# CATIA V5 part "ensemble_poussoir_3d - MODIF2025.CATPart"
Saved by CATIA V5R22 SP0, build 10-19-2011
Part number: Poussoir_flacon
Bounding box of the stored display mesh (mm): x 82 to 187, y 0 to 48, z 0 to 48
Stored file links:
  D:\PER\CAO_PER_MODIF_2025\CAO_PER_pick&place_2024P\Sous_Ensemble_Flacon\Verin\Poussoir_Flacon\ensemble_poussoir_3d - MODIF2025.CATPart
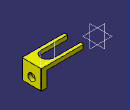
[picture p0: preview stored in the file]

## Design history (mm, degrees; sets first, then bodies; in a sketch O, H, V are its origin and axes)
Set1
  Plane1: type Offset, RefPlane face of Pocket3 from Sketch4.L1, Offset 16, reversed
Body1 (main body)
  Sketch1 on yz-plane, origin (0, 0, 0), H (0, 1, 0), V (0, 0, 1)
    line L1 (0, 0) -> (48, 0)
    line L2 (48, 0) -> (48, 48)
    line L3 (48, 48) -> (0, 48)
    line L4 (0, 48) -> (0, 0)
    point P1 (48, 0)
    point P2 (48, 48)
    point P3 (0, 48)
    distance P1 P2 = 48
    distance P2 P3 = 48
    horizontal: L1 H, L3 H
    vertical: L2 V, L4 V
  Pad1: profile Sketch1, direction (1, 0, 0), length 187
  Sketch2 on face of Pad1 from Sketch1.L4, origin (0, 0, 0), H (1, 0, 0), V (0, 0, 1)
    point P1 (15, 0)
    line L1 (15, 0) -> (173, 0)
    line L2 (173, 0) -> (173, 38)
    line L3 (173, 38) -> (15, 38)
    line L4 (15, 38) -> (15, 0)
    reference projected line E1 (0, 48) -> (187, 48) from edge [face of Pad1 from Sketch1.L4 | face of Pad1 from Sketch1.L3]
    reference projected line E2 (187, 48) -> (187, 0) from edge [face of Pad1 from Sketch1.L4 | end face of Pad1]
    reference projected line E3 (0, 48) -> (0, 0) from edge [start face of Pad1 | face of Pad1 from Sketch1.L4]
    distance L3 E1 = 10
    distance L2 E2 = 14
    distance L4 E3 = 15
    coincidence: P1 H
    horizontal: L1 H, L3 H
    vertical: L2 V, L4 V
  Pocket1: profile Sketch2, direction (0, 1, 0), through (limit type 3)
  Sketch3 on start face of Pad1, origin (0, 0, 0), H (0, -1, 0), V (0, 0, 1)
    line L1 (-41, 0) -> (-7, 0)
    line L2 (-7, 0) -> (-7, 31.5)
    line L3 (-41, 31.5) -> (-41, 0)
    point P2 (-7, 0)
    point P3 (-7, 49)
    point P4 (-41, 49)
    reference projected line E1 (0, 48) -> (0, 0) from edge [start face of Pad1 | face of Pad1 from Sketch1.L4]
    reference projected line E2 (-48, 0) -> (-48, 48) from edge [start face of Pad1 | face of Pad1 from Sketch1.L2]
    reference projected line E3 (0, 0) -> (-48, 0) from edge [start face of Pad1 | face of Pad1 from Sketch1.L1]
    point P5 (-7, 31.5)
    point P6 (-41, 31.5)
    arc A1 centre (-24, 25.5839) radius 18 from (-7, 31.5) to (-41, 31.5) ccw
    point P8 (-7, 31.5)
    point P9 (-41, 31.5)
    distance L2 E1 = 7
    distance L3 E2 = 7
    length L3 = 31.5
    radius A1 = 18
    distance P5 P2 = 31.5
    horizontal: L1 H
    vertical: L2 V, L3 V
    coincidence: E3 L1, L3 P6, L2 P5, P5 P8, P6 P9
  Pocket2: profile Sketch3, direction (1, 0, 0), up to face of Pocket1 from Sketch2.L4
  Sketch4 on face of Pad1 from Sketch1.L3, origin (0, 0, 48), H (1, 0, 0), V (0, 1, 0)
    point P1 (90, 24)
    line L1 (148, 8) -> (28, 8)
    line L2 (28, 40) -> (148, 40)
    point P3 (148, 8)
    point P4 (28, 8)
    arc A1 centre (148, 24) radius 16 from (148, 40) to (148, 8) cw
    arc A2 centre (28, 24) radius 16 from (28, 8) to (28, 40) cw
    point P7 (28, 24)
    reference projected line E1 (0, 48) -> (0, 0) from edge [start face of Pad1 | face of Pad1 from Sketch1.L3]
    distance L1 L2 = 32
    distance P3 P4 = 120
    radius A1 = 16
    radius A2 = 16
    distance P7 E1 = 28
    horizontal: L1 H, L2 H
    equidistance: L1 L2 P1
    fix: P1
  Pocket3: profile Sketch4, direction (0, 0, -1), through (limit type 3)
  Sketch5 on face of Pocket1 from Sketch2.L2, origin (173, 0, 0), H (0, 1, 0), V (0, 0, 1)
    circle A1 centre (24, 18) radius 4.25
    point P1 (24, 18)
    reference projected line E1 (48, 0) -> (48, 48) from edge [face of Pad1 from Sketch1.L2 | end face of Pad1]
    reference projected line E2 (0, 0) -> (48, 0) from edge [face of Pad1 from Sketch1.L1 | end face of Pad1]
    distance P1 E1 = 24
    radius A1 = 4.25
    distance P1 E2 = 18
  Pocket4: profile Sketch5, direction (1, 0, 0), length 7.5, opposite side through (limit type 3)
  Sketch6 on end face of Pad1, origin (187, 0, 0), H (0, 1, 0), V (0, 0, 1)
    circle A1 centre (24, 18) radius 9
    reference projected circle E1 centre (24, 18) radius 4.25 from Sketch5.A1
    radius A1 = 9
    concentricity: E1 A1
  Pocket5: profile Sketch6, direction (-1, 0, 0), length 9
  Sketch7 on face of Pad1 from Sketch1.L3, origin (0, 0, 48), H (1, 0, 0), V (0, 1, 0)
    point P2 (82, 0)
    line L1 (82, 48) -> (0, 48)
    point P3 (0, 48)
    point P4 (0, 48)
    line L2 (0, 48) -> (0, 0)
    point P5 (0, 0)
    line L3 (0, 0) -> (82, 0)
    reference projected line E1 (0, 48) -> (187, 48) from edge [face of Pad1 from Sketch1.L3 | face of Pad1 from Sketch1.L2]
    reference projected line E2 (0, 48) -> (0, 0) from edge [start face of Pad1 | face of Pad1 from Sketch1.L3]
    line L4 (82, 48) -> (82, 0)
    point P6 (82, 0)
    reference projected line E3 (187, 48) -> (187, 0) from edge [face of Pad1 from Sketch1.L3 | end face of Pad1]
    distance E3 L4 = 105
    horizontal: L1 H, L3 H
    coincidence: P5 H, E1 P4, P3 P4, L2 E2, P6 L3, P6 P2
    vertical: L2 V, L4 V
  Pocket6: profile Sketch7, direction (0, 0, -1), length 187
  Chamfer1: length 1, angle 45, on edge [face of Pad1 from Sketch1.L2 | end face of Pad1]
  Chamfer2: length 1, angle 45, on edge [face of Pad1 from Sketch1.L4 | end face of Pad1]
  Chamfer3: length 1, angle 45, on edge [face of Pocket6 from Sketch7.L4 | face of Pad1 from Sketch1.L4]
  Chamfer4: length 1, angle 45, on edge [face of Pad1 from Sketch1.L2 | face of Pocket6 from Sketch7.L4]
